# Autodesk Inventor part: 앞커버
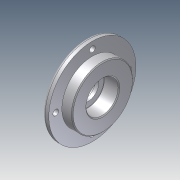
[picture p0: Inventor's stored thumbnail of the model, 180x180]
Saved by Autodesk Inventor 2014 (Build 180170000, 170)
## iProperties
Company: 한국ATC센터
Created: 2014-01
Part Number: 앞커버
Document SubType Name: Modeling
Designer: KYOUNG IL JANG
Density: 2.71 g/cm^3
Material: 알루미늄 6061
Mass: 240.911 g
Surface Area: 235.103 cm^2
Volume: 88.8969 cm^3
Vendor: CBT Solutions
Appearance: 알루미늄 - 평지
Author: KYOUNG IL JANG
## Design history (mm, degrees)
sketch "스케치1"
  geometry: L1 (-15, -35)-(-15, 35) reference; L2 (-15, 35)-(67, 35) reference; L3 (-3, 25)-(-3, -10.613) reference; L4 (0, 0)-(-32, 0); L5 (-3, 0)-(-3, 35); L6 (-3, 35)-(-15, 35); L7 (-15, 35)-(-15, 50); L8 (-15, 50)-(-22, 50); L9 (-22, 50)-(-22, 22.5); L10 (-22, 22.5)-(-32, 22.5); L11 (-32, 22.5)-(-32, 0); L12 (-3, 18.5)-(-20, 18.5); L13 (-20, 18.5)-(-20, 12.5); L14 (-20, 12.5)-(-24, 12.5); L15 (-24, 12.5)-(-24, 16); L16 (-24, 16)-(-32, 16)
  constraints: 28 end point, 7 perpendicular, 6 parallel, 5 point on line, 1 horizontal, 1 other
  dimensions: "d0" = 7 distance of L7.end L8.end; "d1" = 45 diameter of L10 L4; "d2" = 10 distance of L9.end L10.end; "d3" = 37 diameter of L12 L4; "d4" = 17 distance of L12.start L12.end; "d5" = 32 diameter of L16 L4; "d6" = 8 distance of L15.end L16.end; "d7" = 25 diameter of L14 L4; "d8" = 100 diameter of L8 L4
revolve "회전1" sketch "스케치1" stored, may be unused: angle "d9" = 90 deg
fillet "모깎기1" dims "d10" = 3, "d11" = 0.3
chamfer "모따기1" distance "d12" = 1; stored, may be unused: second distance "d13" = 2, angle "d14" = 45 deg
sketch "스케치2"
  geometry: 2 further points
  constraints: 1 vertical alignment
  dimensions: "d15" = 42 distance of point (0, 0) point (0, 42)
hole "구멍1" sketch "스케치2" at (0, 42) diameter "d16" = 6.6; stored, may be unused: countersink angle "d20" = 90 deg, drill point angle "d22" = 118 deg; dims "d17" = 6, "d18" = 4, "d19" = 2, "d21" = 8
node "솔리드1"
pattern_circular "원형 패턴1" dims angle "d24" = 360 deg
node "참조1"
node "참조2"
